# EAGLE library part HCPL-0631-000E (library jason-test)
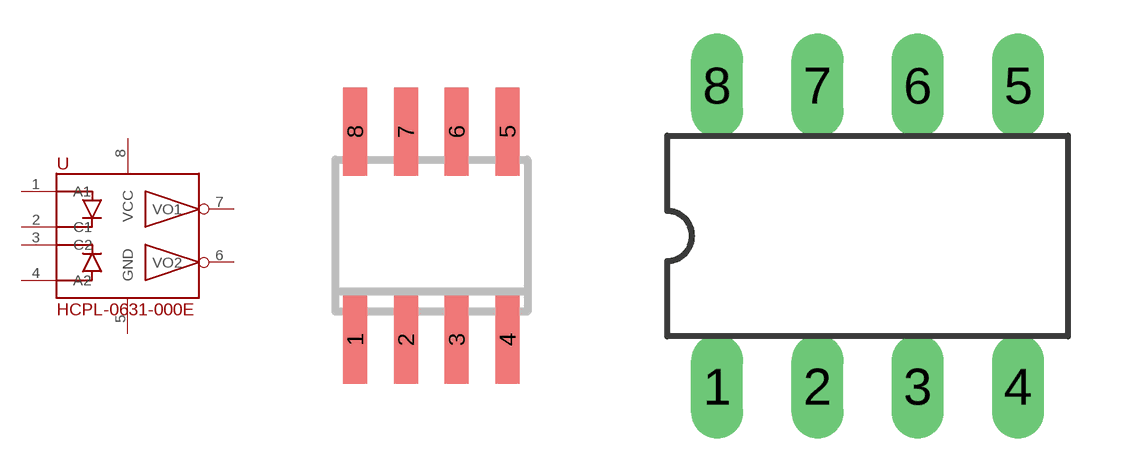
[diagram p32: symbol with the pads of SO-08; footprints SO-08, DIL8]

Designator prefix -

## HCPL-0631-000ESMT  [SO-08]
1  A1  in
2  C1  in
3  C2  in
4  A2  in
5  GND  pwr
6  VO2  out
7  VO1  out
8  VCC  pwr

## HCPL-0631-000EDIL  [DIL8]
Pads as for SO-08

## HCPL-0631-000ESDIL  [DIL8-SMD]
Pads as for SO-08

## Footprint SO-08 (pad centres in mm)
Small Outline Narrow Plastic Gull Wing 150-mil body, package type SN
smd 0.6 x 2.2: 1 -1.905,-2.6; 2 -0.635,-2.6; 3 0.635,-2.6; 4 1.905,-2.6; 5 1.905,2.6; 6 0.635,2.6; 7 -0.635,2.6; 8 -1.905,2.6

## Footprint DIL8 (pad centres in mm)
Dual In Line package type P
drill 0.813 long: 1 -3.81,-3.81; 2 -1.27,-3.81; 3 1.27,-3.81; 4 3.81,-3.81; 5 3.81,3.81; 6 1.27,3.81; 7 -1.27,3.81; 8 -3.81,3.81

## Footprint DIL8-SMD (pad centres in mm)
smd 1 x 1.5: 1 -4.763,3.81; 2 -4.763,1.27; 3 -4.763,-1.27; 4 -4.763,-3.81; 5 4.763,-3.81; 6 4.763,-1.27; 7 4.763,1.27; 8 4.763,3.81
